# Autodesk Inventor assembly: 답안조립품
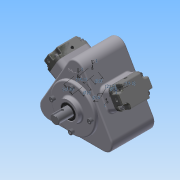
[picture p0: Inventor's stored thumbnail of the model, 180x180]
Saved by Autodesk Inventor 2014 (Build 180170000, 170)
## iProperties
Created: 2015-06
Part Number: 답안조립품
Document SubType Name: Assembly
Designer: Administrator
Mass: 5318.58 g
Surface Area: 2414.93 cm^2
Volume: 1564.62 cm^3
Density: 3.39928 g/cm^3
Author: Administrator
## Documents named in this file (20)
- C:\Documents and Settings\MYHOME\바탕 화면\350605V1043\답안조립품.iam
- C:\Documents and Settings\MYHOME\바탕 화면\350605V1043\본체.ipt
- C:\Documents and Settings\MYHOME\바탕 화면\350605V1043\베어링 NA 4904.ipt
- 베어링 NA 4904.ipt
- C:\Documents and Settings\MYHOME\바탕 화면\350605V1043\편심축.ipt
- C:\Documents and Settings\MYHOME\바탕 화면\350605V1043\앞커버.ipt
- C:\Documents and Settings\MYHOME\바탕 화면\350605V1043\오일실.ipt
- 오일실.ipt
- C:\Documents and Settings\MYHOME\바탕 화면\350605V1043\M6x0.7x20.ipt
- M6x0.7x20.ipt
- C:\Documents and Settings\MYHOME\바탕 화면\350605V1043\부시.ipt
- C:\Documents and Settings\MYHOME\바탕 화면\350605V1043\헤더커버.ipt
- 헤더커버.ipt
- C:\Documents and Settings\MYHOME\바탕 화면\350605V1043\M4x0.5x16.ipt
- M4x0.5x16.ipt
- C:\Documents and Settings\MYHOME\바탕 화면\350605V1043\슬라이드.ipt
- C:\Documents and Settings\MYHOME\바탕 화면\350605V1043\11 - 스프링.ipt
- C:\Documents and Settings\MYHOME\바탕 화면\350605V1043\8 - 스프링.ipt
- C:\Documents and Settings\MYHOME\바탕 화면\350605V1043\9 - 스프링.ipt
- C:\Documents and Settings\MYHOME\바탕 화면\350605V1043\10 - 스프링.ipt
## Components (14 placed, 3 different names)
1. 헤더커버:1
2. 헤더커버:2
3. M4x0.5x16:1
4. M4x0.5x16:2
5. M4x0.5x16:3
6. M4x0.5x16:4
7. M4x0.5x16:5
8. M4x0.5x16:6
9. M4x0.5x16:7
10. M4x0.5x16:8
11. M6x0.7x20:1
12. M6x0.7x20:2
13. M6x0.7x20:3
14. M6x0.7x20:4
